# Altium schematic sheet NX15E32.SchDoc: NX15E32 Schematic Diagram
size A3; DocumentNumber: 2; SheetNumber: 2; SheetTotal: 2
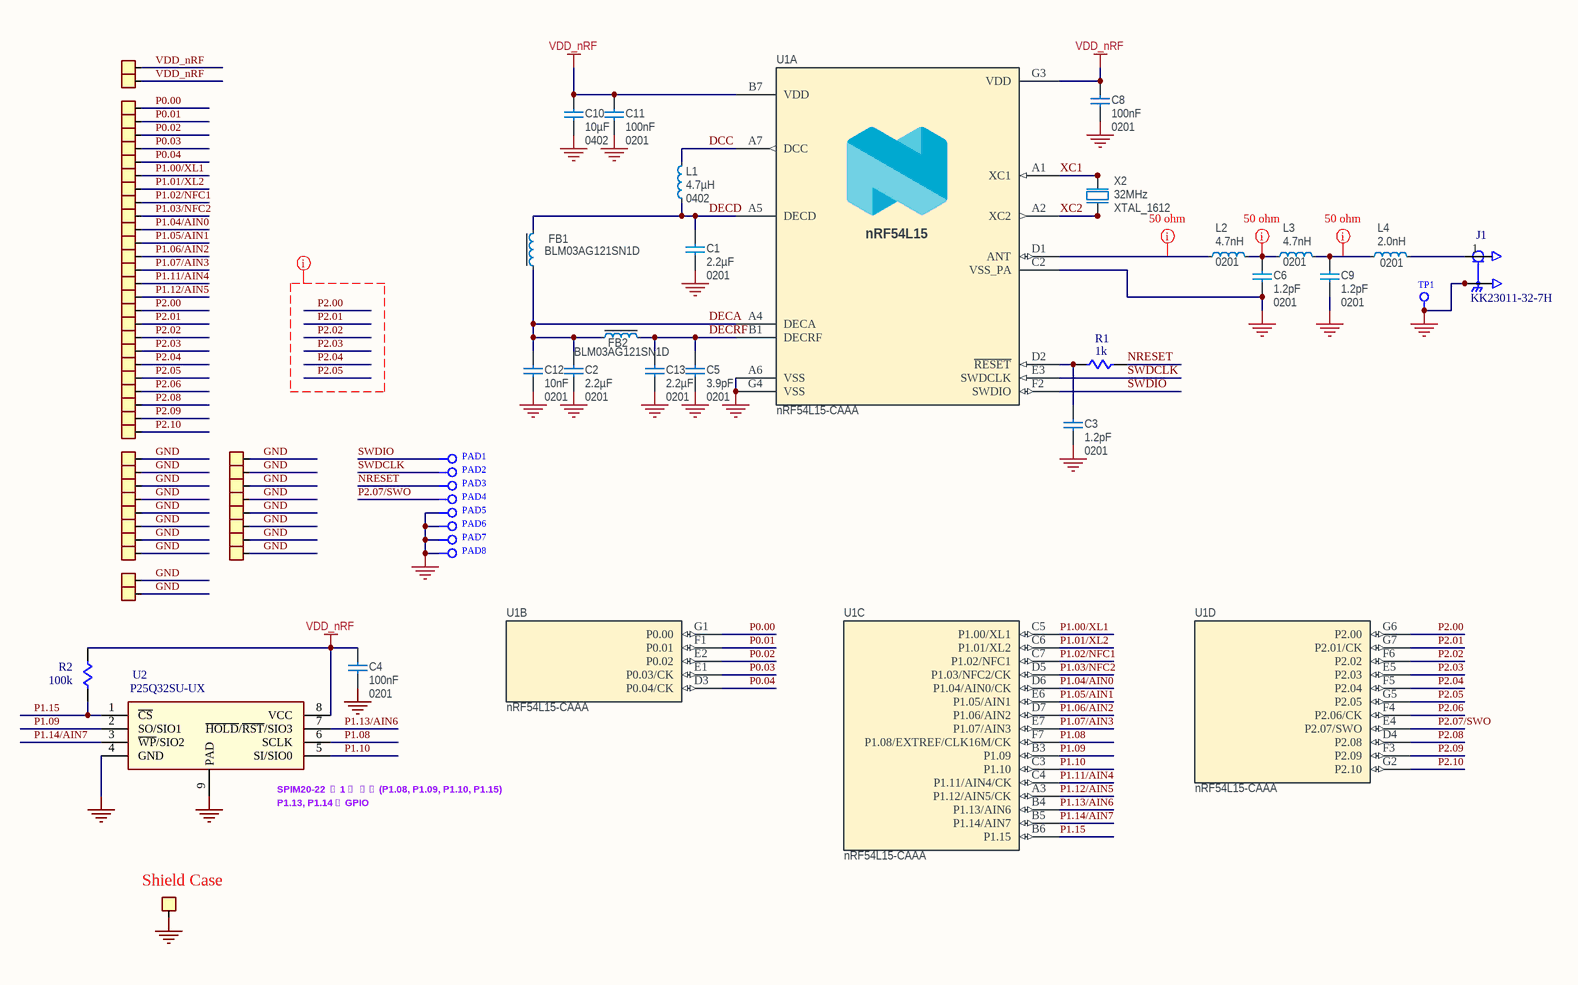
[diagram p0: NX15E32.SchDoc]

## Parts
C1  2.2µF  Footprint Doc: 0201  [CAP 0201/0603X03L_C]
C2  2.2µF  Footprint Doc: 0201  [CAP 0201/0603X03L_C]
C3  1.2pF  Footprint Doc: 0201  [CAP 0201/0603X03L_C]
C4  100nF  Footprint Doc: 0201  [CAP 0201/0603X03L_C]
C5  3.9pF  Footprint Doc: 0201  [CAP 0201/0603X03L_C]
C6  1.2pF  Footprint Doc: 0201  [CAP 0201/0603X03L_C]
C8  100nF  Footprint Doc: 0201  [CAP 0201/0603X03L_C]
C9  1.2pF  Footprint Doc: 0201  [CAP 0201/0603X03L_C]
C10  10µF  Footprint Doc: 0402  [CAP 0402/1005 RF]
C11  100nF  Footprint Doc: 0201  [CAP 0201/0603X03L_C]
C12  10nF  Footprint Doc: 0201  [CAP 0201/0603X03L_C]
C13  2.2µF  Footprint Doc: 0201  [CAP 0201/0603X03L_C]
FB1  BLM03AG121SN1D  [INDC0603X03L_C]
FB2  BLM03AG121SN1D  [INDC0603X03L_C]
J1  KK23011-32-7H  [IPEX 3x3_23011]
L1  4.7µH  Footprint Doc: 0402  [IND 0402/1005 RF]
L2  4.7nH  Footprint Doc: 0201  [INDC0603X03L_C]
L3  4.7nH  Footprint Doc: 0201  [INDC0603X03L_C]
L4  2.0nH  Footprint Doc: 0201  [INDC0603X03L_C]
P1  PAD SQUARE  [PAD_0.6X0.3]  (value not drawn)
P2  PAD SQUARE  [PAD_0.6X0.3]  (value not drawn)
P3  PAD SQUARE  [PAD_0.6X0.3]  (value not drawn)
P4  PAD SQUARE  [PAD_0.6X0.3]  (value not drawn)
P5  PAD SQUARE  [PAD_0.6X0.3]  (value not drawn)
P6  PAD SQUARE  [PAD_0.6X0.3]  (value not drawn)
P7  PAD SQUARE  [PAD_0.6X0.3]  (value not drawn)
P8  PAD SQUARE  [PAD_0.6X0.3]  (value not drawn)
P9  PAD SQUARE  [PAD_0.6X0.3]  (value not drawn)
P10  PAD SQUARE  [PAD_0.6X0.3]  (value not drawn)
P11  PAD SQUARE  [PAD_0.6X0.3]  (value not drawn)
P12  PAD SQUARE  [PAD_0.6X0.3]  (value not drawn)
P13  PAD SQUARE  [PAD_0.6X0.3]  (value not drawn)
P14  PAD SQUARE  [PAD_0.6X0.3]  (value not drawn)
P15  PAD SQUARE  [PAD_0.6X0.3]  (value not drawn)
P16  PAD SQUARE  [PAD_0.6X0.3]  (value not drawn)
P17  PAD SQUARE  [PAD_0.6X0.3]  (value not drawn)
P18  PAD SQUARE  [PAD_0.6X0.3]  (value not drawn)
P19  PAD SQUARE  [PAD_0.6X0.3]  (value not drawn)
P20  PAD SQUARE  [PAD_0.6X0.3]  (value not drawn)
P21  PAD SQUARE  [PAD_0.6X0.3]  (value not drawn)
P22  PAD SQUARE  [PAD_0.6X0.3]  (value not drawn)
P23  PAD SQUARE  [PAD_0.6X0.3]  (value not drawn)
P24  PAD SQUARE  [PAD_0.6X0.3]  (value not drawn)
P25  PAD SQUARE  [PAD_0.6X0.3]  (value not drawn)
P26  PAD SQUARE  [PAD_0.6X0.3]  (value not drawn)
P27  PAD SQUARE  [PAD_0.6X0.3]  (value not drawn)
P28  PAD SQUARE  [PAD_0.6X0.3]  (value not drawn)
P29  PAD SQUARE  [PAD_0.6X0.3]  (value not drawn)
P30  PAD SQUARE  [PAD_0.6X0.3]  (value not drawn)
P31  PAD SQUARE  [PAD_0.6X0.3]  (value not drawn)
P32  PAD SQUARE  [PAD_0.6X0.3]  (value not drawn)
P33  PAD SQUARE  [PAD_0.6X0.3]  (value not drawn)
P34  PAD SQUARE  [PAD_0.6X0.3]  (value not drawn)
P35  PAD SQUARE  [PAD_0.6X0.3]  (value not drawn)
P36  PAD SQUARE  [PAD_0.6X0.3]  (value not drawn)
P37  PAD SQUARE  [PAD_0.6X0.3]  (value not drawn)
P38  PAD SQUARE  [PAD_0.6X0.3]  (value not drawn)
P39  PAD SQUARE  [PAD_0.6X0.3]  (value not drawn)
P40  PAD SQUARE  [PAD_0.6X0.3]  (value not drawn)
P41  PAD SQUARE  [PAD_0.6X0.3]  (value not drawn)
P42  PAD SQUARE  [PAD_0.6X0.3]  (value not drawn)
P43  PAD SQUARE  [PAD_0.6X0.3]  (value not drawn)
P44  PAD SQUARE  [PAD_0.6X0.3]  (value not drawn)
P45  PAD SQUARE  [PAD_0.6X0.3]  (value not drawn)
PAD1  5010  [pad_0.6x0.6]  (value not drawn)  (no BOM)
PAD2  5010  [pad_0.6x0.6]  (value not drawn)  (no BOM)
PAD3  5010  [pad_0.6x0.6]  (value not drawn)  (no BOM)
PAD4  5010  [pad_0.6x0.6]  (value not drawn)  (no BOM)
PAD5  5010  [pad_0.6x0.6]  (value not drawn)  (no BOM)
PAD6  5010  [pad_0.6x0.6]  (value not drawn)  (no BOM)
PAD7  5010  [pad_0.6x0.6]  (value not drawn)  (no BOM)
PAD8  5010  [pad_0.6x0.6]  (value not drawn)  (no BOM)
R1  1k  [RES 0201/0603X03L_C]
R2  100k  [RES 0201/0603X03L_C]
T1  SHILED CASE  [Shield_can_Korlinx]  (value not drawn)  (no BOM)
TP1  5010  [TP / 0.3]  (value not drawn)  (no BOM)
U1  nRF54L15-CAAA  [BGA49C30P7x7_2245X2451X48]  (parts A,B,C,D of 4)
U2  P25Q32SU-UX  [USON-8 2X3 /PSON50P300X200X60-9N]
X2  32MHz  Footprint Doc: XTAL_1612  [XTAL/1612]

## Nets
GND: C1.1 C2.1 C3.1 C4.1 C5.1 C6.1 C8.2 C9.1 C10.1 C11.2 C12.1 C13.1 J1.2(GND) J1.3(GND) P18.1 P28.1 P29.1 P30.1 P31.1 P32.1 P33.1 P34.1 P35.1 P36.1 P37.1 P38.1 P39.1 P40.1 P41.1 P43.1 P44.1 P45.1 PAD5.1 PAD6.1 PAD7.1 PAD8.1 T1.1 TP1.1 U1.A6(VSS) U1.C2(VSS_PA) U1.G4(VSS) U2.4(GND) U2.9(PAD) X2.2(GND) X2.4(GND)
VDD_nRF: C4.2 C8.1 C10.2 C11.1 P1.1 P2.1 R2.2 U1.B7(VDD) U1.G3(VDD) U2.8(VCC)
DCC: L1.1 U1.A7(DCC)
DECA: C2.2 C12.2 FB1.2 FB2.2 U1.A4(DECA)
DECD: C1.2 FB1.1 L1.2 U1.A5(DECD)
DECRF: C5.2 C13.2 FB2.1 U1.B1(DECRF)
NRESET: PAD3.1 R1.2
P0.00: P15.1 U1.G1(P0.00)
P0.01: P14.1 U1.F1(P0.01)
P0.02: P3.1 U1.E2(P0.02)
P0.03: P4.1 U1.E1(P0.03/CK)
P0.04: P5.1 U1.D3(P0.04/CK)
P1.00/XL1: P6.1 U1.C5(P1.00/XL1)
P1.01/XL2: P7.1 U1.C6(P1.01/XL2)
P1.02/NFC1: P8.1 U1.C7(P1.02/NFC1)
P1.03/NFC2: P9.1 U1.D5(P1.03/NFC2/CK)
P1.04/AIN0: P10.1 U1.D6(P1.04/AIN0/CK)
P1.05/AIN1: P11.1 U1.E6(P1.05/AIN1)
P1.06/AIN2: P12.1 U1.D7(P1.06/AIN2)
P1.07/AIN3: P13.1 U1.E7(P1.07/AIN3)
P1.08: U1.F7(P1.08/EXTREF/CLK16M/CK) U2.6(SCLK)
P1.09: U1.B3(P1.09) U2.2(SO/SIO1)
P1.10: U1.C3(P1.10) U2.5(SI/SIO0)
P1.11/AIN4: P16.1 U1.C4(P1.11/AIN4/CK)
P1.12/AIN5: P17.1 U1.A3(P1.12/AIN5/CK)
P1.13/AIN6: U1.B4(P1.13/AIN6) U2.7(~{HOLD}/~{RST}/SIO3)
P1.14/AIN7: U1.B5(P1.14/AIN7) U2.3(~{WP}/SIO2)
P1.15: R2.1 U1.B6(P1.15) U2.1(~{CS})
P2.00: P20.1 U1.G6(P2.00)
P2.01: P19.1 U1.G7(P2.01/CK)
P2.02: P42.1 U1.F6(P2.02)
P2.03: P22.1 U1.E5(P2.03)
P2.04: P21.1 U1.F5(P2.04)
P2.05: P26.1 U1.G5(P2.05)
P2.06: P24.1 U1.F4(P2.06/CK)
P2.07/SWO: PAD4.1 U1.E4(P2.07/SWO)
P2.08: P23.1 U1.D4(P2.08)
P2.09: P25.1 U1.F3(P2.09)
P2.10: P27.1 U1.G2(P2.10)
SWDCLK: PAD2.1 U1.E3(SWDCLK)
SWDIO: PAD1.1 U1.F2(SWDIO)
XC1: U1.A1(XC1) X2.1(inp)
XC2: U1.A2(XC2) X2.3(out)
NetC3_2: C3.2 R1.1 U1.D2(~{RESET})
NetC6_2: C6.2 L2.2 L3.1
NetC9_2: C9.2 L3.2 L4.1
NetJ1_1: J1.1(SIGNAL) L4.2
NetL2_1: L2.1 U1.D1(ANT)

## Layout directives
net class 50 ohm: NetC6_2, NetC9_2, NetL2_1
net class QSPI: P2.00, P2.01, P2.02, P2.03, P2.04, P2.05

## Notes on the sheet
- (near U2) SPIM20-22 중 1개 사용 (P1.08, P1.09, P1.10, P1.15)
- (near U2) P1.13, P1.14는 GPIO
- (near T1) Shield Case

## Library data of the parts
C1 C2 C13 = C0201-2µ2-2.5V-X6T-GRM033D80E225ME47D: Capacitor, Ceramic, 2.2µF 2.5V X6T 0201,±20%; Manufacturer: Murata; Manufacturer Part Number: GRM033R61A225KE47; Part number NEMS: 100200527; Component Status: Active; Pad Count: 2; Note: 2.5V, 20%, X6T; Artikkelnr Noca: N.A.
C3 C6 C9 = C0201-1.2p-HQ-Murata: Capacitor, NP0, ±0.05pF, 50V; Manufacturer: Murata; Manufacturer Part Number: GJM0335C1H1R2WB01D; Part number NEMS: 100200457; Component Status: Active; Pad Count: 2; Artikkelnr Noca: N.A.
C4 C12 = C0201-10n-6.3V-X7R: Capacitor, X7R, 6.3V; Manufacturer: Murata; Manufacturer Part Number: GRM033R70J103KA01D; Part number NEMS: 100200407; Component Status: Active; Pad Count: 2; Artikkelnr Noca: N.A.
C5 = C0201-3.9p-HQ-Murata: Capacitor, NP0, ±0.05pF, 25V; Manufacturer: Murata; Manufacturer Part Number: GJM0333C1E3R9WB01; Part number NEMS: 100200424; Component Status: Active; Pad Count: 2; Artikkelnr Noca: N.A.
C8 C11 = C0201-100n-10V-X7R: Capacitor, X7R, ±10%; Manufacturer: N.A.; Part number NEMS: 100200469; Note: 10V; Pad Count: 2; Component Status: Active
C10 = C0402-10µF-6.3V-X6S: Capacitor, X6S, ±20%, 6.3V; Manufacturer: N.A.; Part number NEMS: 100200478; Component Status: Active; Pad Count: 2
FB1 FB2 = FB0201-120R@100M-200mA-BLM03AG121SN1D: Ferrite Bead, 120 Ohm @ 100MHz, 200mA, 500 mOhm Max; Manufacturer: Murata; Part number NEMS: 100300419; Component Status: Active; Pad Count: 2; Value: 120R/0.2A; Artikkelnr Noca: N.A.
J1 = 20449-001E-03: IPEX Connector; MF: I-PEX
L1 = L0402-4µ7-PLEA67BCA4R7M-1PT00: Inductor, 300mA, ±20%, 1.08R; Manufacturer: TDK Corporation; Part number NEMS: 100300441; Component Status: Active; Pad Count: 2; Note: Power Inductor ±20%; Artikkelnr Noca: N.A.
L2 L3 = L0201-4n7-HQ-Murata: Inductor, 400mA, ±3%, 250mOhm; Manufacturer: Murata; Manufacturer Part Number: LQP03HQ4N7H02; Part number NEMS: 100300231; Component Status: Active; Pad Count: 2; Note: -55°C ~ 125°C; Artikkelnr Noca: N.A.
L4 = L0201-2n0-HQ-Murata: Inductor, 600mA, ±0.1ｎH, 120mOhm; Manufacturer: Murata; Manufacturer Part Number: LQP03HQ2N0B02; Part number IPS: 00000001670; Part number NEMS: 100300207; Component Status: Active; Pad Count: 2; Note: -55°C ~ 125°C; Artikkelnr Noca: N.A.
PAD1-PAD8 TP1 = TP: Test Point; Manufacturer: Keystone; CompType: Test Point Loop; ContactFinish: Silver
R1 = Res1: Resistor
R2 = Res1: Resistor; Value: 1K
T1 = PAD SQUARE
U1 = nRF54L15-CAAA: Multi-protocol Bluetooth Low Energy, IEEE 802.15.4, ANT and 2.4GHz proprietary Wireless MCU; Manufacturer: Nordic Semiconductor; Part number NEMS: 102000283; Component Status: Active; Pad Count: 46; Note: N.A.
U2 = P25Q32SU: Flash Memory
X2 = XTAL_SMD1612_32MHz_8pF_Kyocera: Crystal; Manufacturer Part Number: CX1612DB32000D0WZRC3; Part number NEMS: 101600029; Component Status: Active; Pad Count: 4; Note: XTAL SMD 32.000MHz; Artikkelnr Noca: N.A.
